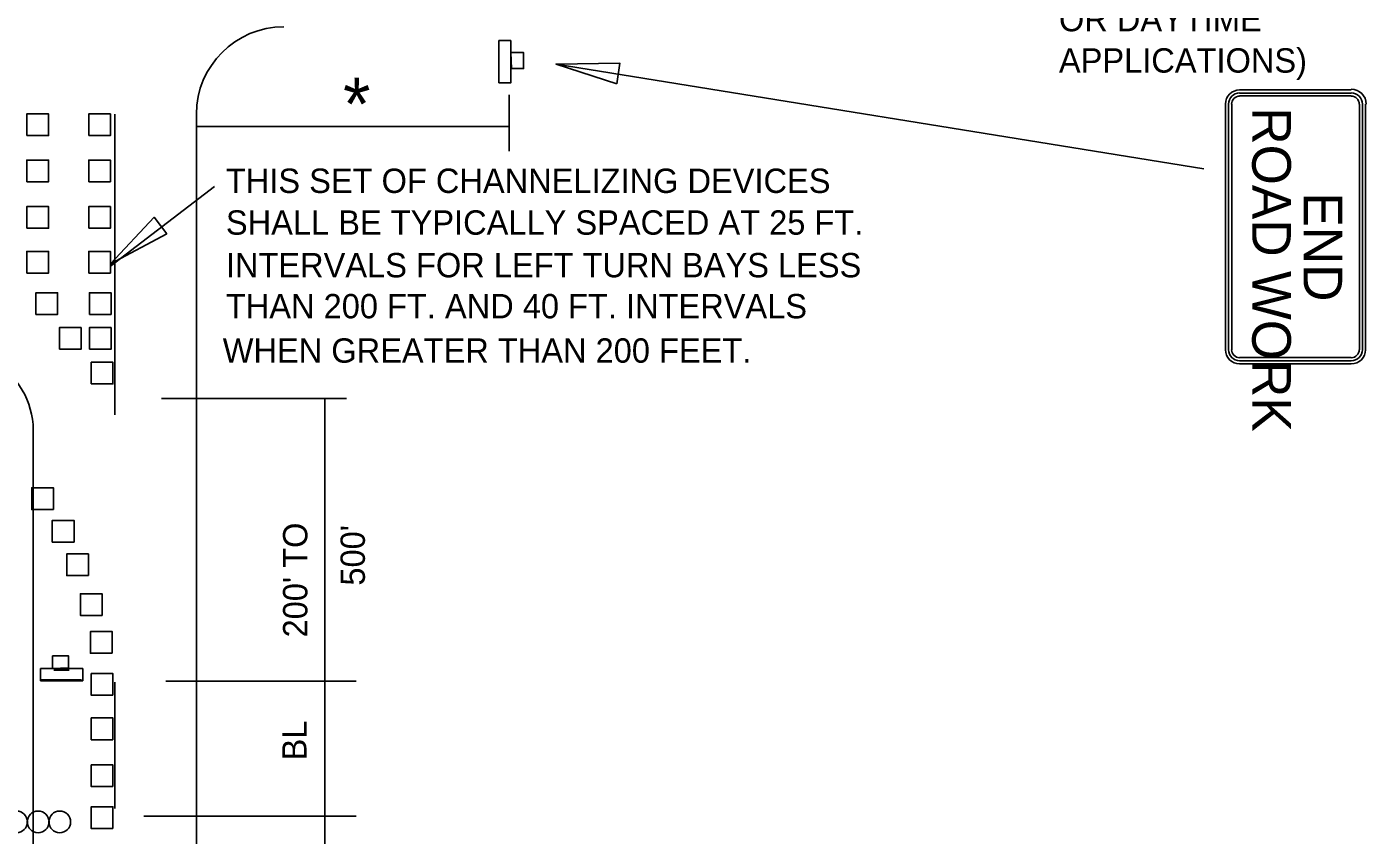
# Model space of a CAD drawing. Extents: x 1531.4 to 1538.6, y 1528.5 to 1539.8.
# Drawn here: x 1534.932 to 1538.231, y 1533.958 to 1535.949 of the extents above; entities that cross this region are included whole.
import ezdxf

# ---------------------------------------------------------------- set-up
doc = ezdxf.new("R2010")
doc.units = 0
for name, color, linetype in [('DETL-DIMS', 7, 'Continuous'), ('DETL-LINE', 7, 'Continuous'), ('DETL-NOTE', 7, 'Continuous'), ('USER-BORD', 7, 'Continuous')]:
    doc.layers.add(name, color=color, linetype=linetype)

# ---------------------------------------------------------------- blocks, each defined once
blk = doc.blocks.new('CD2')
at = {"layer": 'USER-BORD'}
blk.add_lwpolyline([(-0.0062, -0.0062), (0, -0.0062), (0, 0), (-0.0062, 0)], close=True, dxfattribs=at)
blk = doc.blocks.new('PANEL')
at = {"layer": 'USER-BORD'}
for centre in [(0.00309, -0.00012), (0.00928, -0.00012), (0.01546, -0.00012)]:
    blk.add_circle(centre, 0.00312, dxfattribs=at)
blk = doc.blocks.new('AWS')
at = {"layer": 'USER-BORD'}
for p, q in [((-0.0027, 0.0017), (0.0017, 0.0017)), ((-0.0063, -0.0011), (0.0052, -0.0011))]:
    blk.add_line(p, q, dxfattribs=at)
blk = doc.blocks.new('SIGN')
at = {"layer": 'USER-BORD'}
for points in [[(-0.0013, 0.0018), (0.0011, 0.0019), (0.0011, 0.0037), (-0.0013, 0.0037)], [(-0.0031, 0.0018), (-0.0031, 0), (0.0032, 0), (0.0032, 0.0018)]]:
    blk.add_lwpolyline(points, close=True, dxfattribs=at)

msp = doc.modelspace()

# ---------------------------------------------------------------- linework, layer by layer
at = {"layer": 'DETL-DIMS'}
for p, q in [((1536.2358, 1535.8571), (1537.831, 1535.5991)), ((1536.1205, 1535.7815), (1536.1205, 1535.6424)), ((1535.3502, 1535.7037), (1536.1205, 1535.7037)), ((1535.3948, 1535.5556), (1535.1383, 1535.3599)), ((1535.2641, 1535.0336), (1535.7198, 1535.0336)), ((1535.6664, 1535.0336), (1535.6664, 1534.3372)), ((1535.2744, 1534.3372), (1535.7432, 1534.3372)), ((1535.6664, 1534.3372), (1535.6664, 1531.4196)), ((1535.2209, 1534.0047), (1535.7432, 1534.0047))]:
    msp.add_line(p, q, dxfattribs=at)
for points in [[(1536.3853, 1535.8082), (1536.3931, 1535.8593), (1536.2358, 1535.8571)], [(1535.2773, 1535.4389), (1535.2459, 1535.48), (1535.1383, 1535.3653)]]:
    msp.add_lwpolyline(points, close=True, dxfattribs=at)
at = {"layer": 'DETL-LINE'}
for p, q in [((1537.9191, 1535.7942), (1538.1941, 1535.7942)), ((1537.9191, 1535.7861), (1537.9191, 1535.786)), ((1537.9191, 1535.7861), (1537.9191, 1535.786)), ((1537.9191, 1535.786), (1538.1941, 1535.786)), ((1537.9191, 1535.786), (1538.1941, 1535.786)), ((1538.1941, 1535.7787), (1537.9191, 1535.7787)), ((1537.9191, 1535.7787), (1538.1941, 1535.7787)), ((1537.9191, 1535.7783), (1537.9191, 1535.7787)), ((1537.884, 1535.1538), (1537.884, 1535.7587)), ((1537.8917, 1535.1538), (1537.8917, 1535.7587)), ((1537.8917, 1535.1538), (1537.8917, 1535.7587)), ((1537.8995, 1535.7587), (1537.8995, 1535.1538)), ((1537.8995, 1535.1538), (1537.8995, 1535.7587)), ((1538.2141, 1535.1538), (1538.2141, 1535.7587)), ((1538.2141, 1535.7587), (1538.2141, 1535.1538)), ((1538.2214, 1535.7587), (1538.2214, 1535.1538)), ((1538.2214, 1535.7587), (1538.2214, 1535.1538)), ((1538.2291, 1535.7587), (1538.2291, 1535.1538)), ((1535.1495, 1535.7337), (1535.1495, 1534.9936)), ((1535.3501, 1533.1768), (1535.3501, 1535.7337)), ((1537.9191, 1535.1342), (1538.1941, 1535.1342)), ((1538.1941, 1535.1342), (1537.9191, 1535.1342)), ((1538.1941, 1535.1262), (1537.9191, 1535.1262)), ((1538.1941, 1535.1262), (1537.9191, 1535.1262)), ((1538.1941, 1535.1187), (1537.9191, 1535.1187)), ((1534.9479, 1534.9696), (1534.9479, 1534.9264)), ((1534.9479, 1534.9264), (1534.9479, 1534.873)), ((1534.9479, 1533.1768), (1534.9479, 1534.873)), ((1535.1495, 1534.3346), (1535.1495, 1534.0237))]:
    msp.add_line(p, q, dxfattribs=at)
for centre, radius, start, end in [((1535.5654, 1535.7337), 0.2154, 90, 180), ((1537.9191, 1535.7586), 0.0351, 90, 180), ((1537.9191, 1535.7586), 0.0275, 90, 180), ((1537.9191, 1535.7586), 0.0275, 90, 180), ((1537.9191, 1535.7586), 0.0197, 90, 180), ((1537.9191, 1535.7586), 0.0197, 90, 180), ((1538.194, 1535.7586), 0.0368, 0, 90), ((1538.194, 1535.7586), 0.0275, 0, 90), ((1538.194, 1535.7586), 0.0275, 0, 90), ((1538.194, 1535.7586), 0.0197, 0, 90), ((1538.194, 1535.7586), 0.0197, 0, 90), ((1537.9191, 1535.1538), 0.0351, 180, 270), ((1537.9191, 1535.1538), 0.0275, 180, 270), ((1537.9191, 1535.1538), 0.0275, 180, 270), ((1537.9191, 1535.1538), 0.0197, 180, 270), ((1537.9191, 1535.1538), 0.0197, 180, 270), ((1538.194, 1535.1538), 0.0197, 270, 0), ((1538.194, 1535.1538), 0.0275, 270, 0), ((1538.194, 1535.1538), 0.0351, 270, 0), ((1538.194, 1535.1538), 0.0275, 270, 0), ((1538.194, 1535.1538), 0.0197, 270, 0), ((1534.7476, 1534.9534), 0.2007, 4.57, 63.0108)]:
    msp.add_arc(centre, radius, start, end, dxfattribs=at)

# ---------------------------------------------------------------- block references
for name, p, xscale, yscale, rotation in [('SIGN', (1536.0948, 1535.8641), 16.482020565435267, 16.482020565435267, -90.00000000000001), ('CD2', (1534.9445, 1534.8135), 8.61495264, -8.61495264, 180), ('CD2', (1534.9952, 1534.7334), 8.61495264, -8.61495264, 180), ('CD2', (1535.0306, 1534.6507), 8.61495264, -8.61495264, 180), ('CD2', (1535.0642, 1534.5525), 8.61495264, -8.61495264, 180), ('CD2', (1535.0892, 1534.4594), 8.61495264, -8.61495264, 180), ('CD2', (1535.0909, 1534.3561), 8.61495264, -8.61495264, 180), ('CD2', (1535.0909, 1534.2466), 8.61495264, -8.61495264, 180), ('CD2', (1535.0909, 1534.1312), 8.61495264, -8.61495264, 180), ('CD2', (1535.0909, 1534.0278), 8.61495264, -8.61495264, 180), ('PANEL', (1535.0401, 1533.9916), 8.61495264, -8.61495264, 180)]:
    msp.add_blockref(name, p, dxfattribs=dict(at, xscale=xscale, yscale=yscale, rotation=rotation))
for name, p, xscale, yscale in [('CD2', (1534.9858, 1535.7344), 8.61495264, 8.61495264), ('CD2', (1535.1383, 1535.7344), 8.61495264, 8.61495264), ('CD2', (1534.9858, 1535.6208), 8.61495264, 8.61495264), ('CD2', (1535.1383, 1535.6208), 8.61495264, 8.61495264), ('CD2', (1534.9858, 1535.5061), 8.61495264, 8.61495264), ('CD2', (1535.1383, 1535.5061), 8.61495264, 8.61495264), ('CD2', (1534.9858, 1535.3959), 8.61495264, 8.61495264), ('CD2', (1535.1383, 1535.3959), 8.61495264, 8.61495264), ('CD2', (1535.0081, 1535.2942), 8.61495264, 8.61495264), ('CD2', (1535.14, 1535.2942), 8.61495264, 8.61495264), ('CD2', (1535.0659, 1535.2081), 8.61495264, 8.61495264), ('CD2', (1535.14, 1535.2081), 8.61495264, 8.61495264), ('CD2', (1535.1443, 1535.1228), 8.61495264, 8.61495264), ('SIGN', (1535.0172, 1534.3385), 16.482020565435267, 16.482020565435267), ('AWS', (1535.022, 1534.35), 8.61495264, 8.61495264)]:
    msp.add_blockref(name, p, dxfattribs=dict(at, xscale=xscale, yscale=yscale))

# ---------------------------------------------------------------- texts
for s, p in [('ROAD WORK', (1537.9501, 1535.7508)), ('END', (1538.0766, 1535.5414))]:
    msp.add_text(s, height=0.09521, rotation=270, dxfattribs=at).set_placement(p)
at = {"layer": 'DETL-NOTE'}
for s, height, p in [('OR DAYTIME', 0.06, (1537.4741, 1535.938)), ('APPLICATIONS)', 0.06, (1537.4741, 1535.8362)), ('*', 0.1292, (1535.7112, 1535.6943)), ('THIS SET OF CHANNELIZING DEVICES', 0.06, (1535.4226, 1535.5398)), ('SHALL BE TYPICALLY SPACED AT 25 FT. ', 0.06, (1535.4227, 1535.437)), ('INTERVALS FOR LEFT TURN BAYS LESS', 0.06, (1535.4226, 1535.332)), ('THAN 200 FT. AND 40 FT. INTERVALS', 0.06, (1535.4226, 1535.231)), ('WHEN GREATER THAN 200 FEET.', 0.06, (1535.4148, 1535.1217))]:
    msp.add_text(s, height=height, dxfattribs=at).set_placement(p)
for s, p in [("200' TO", (1535.6233, 1534.445)), ("500'", (1535.765, 1534.5727)), ('BL', (1535.6213, 1534.1421))]:
    msp.add_text(s, height=0.06, rotation=90, dxfattribs=at).set_placement(p)

doc.saveas('drawing.dxf')
